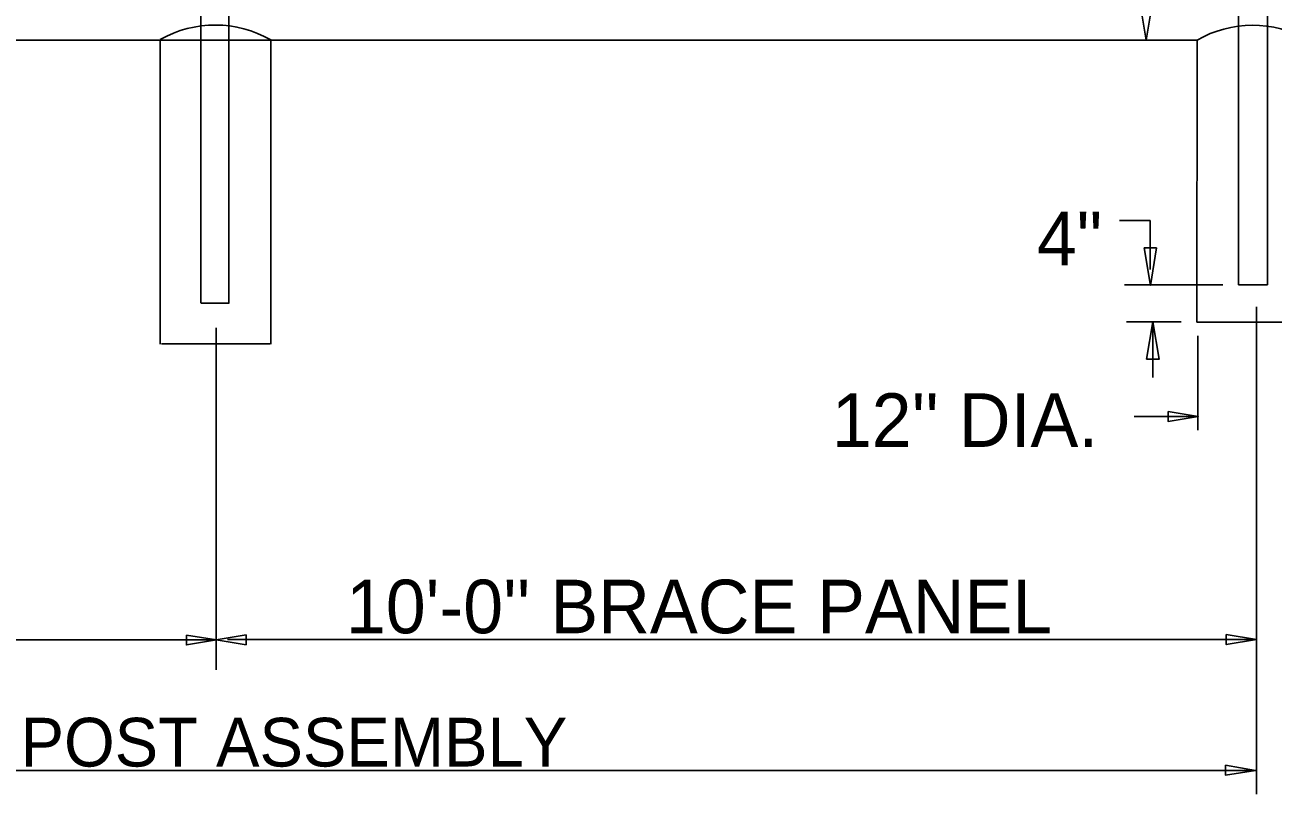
# Model space of a CAD drawing. Extents: x 0 to 1270, y 0 to 830.
# Drawn here: x 1008.4 to 1122.5, y 308.8 to 379.2 of the extents above; entities that cross this region are included whole.
import ezdxf

# ---------------------------------------------------------------- set-up
doc = ezdxf.new("R2010")
doc.units = 0
for name, color, linetype in [('CT_CSHT_GeneralLabel', 7, 'Continuous'), ('CT_Dimensions', 7, 'Continuous'), ('sb_Chainlink Fence', 7, 'Continuous'), ('sb_Existing Concrete', 7, 'Continuous'), ('sb_Existing Structural Steel', 7, 'Continuous')]:
    doc.layers.add(name, color=color, linetype=linetype)

msp = doc.modelspace()

# ---------------------------------------------------------------- linework, layer by layer
at = {"layer": 'CT_Dimensions'}
for p, q in [((1108.44, 361.28), (1111.25, 361.28)), ((1111.25, 356.79), (1111.25, 361.28)), ((1108.91, 355.39), (1117.9, 355.39)), ((1120.99, 339.02), (1120.97, 353.38)), ((1109.09, 352), (1114.08, 352)), ((1111.5, 346.91), (1111.5, 351.99)), ((1025.86, 320.16), (1025.86, 351.44)), ((1115.62, 342.09), (1115.62, 350.72)), ((1109.8, 343.34), (1115.62, 343.34)), ((1120.97, 315.98), (1120.99, 339.02)), ((1120.97, 308.8), (1120.97, 325.43)), ((928.66, 322.9), (1025.84, 322.9)), ((1026.87, 322.93), (1120.97, 322.93)), ((930.83, 310.95), (1120.83, 310.95))]:
    msp.add_line(p, q, dxfattribs=at)
for points in [[(1111.35, 380.5), (1110.89, 377.75), (1110.43, 380.5)], [(1111.85, 358.76), (1111.28, 355.33), (1110.71, 358.76)], [(1110.93, 348.57), (1111.5, 352), (1112.08, 348.57)], [(1112.9, 343.8), (1115.65, 343.34), (1112.9, 342.89)], [(1023.13, 323.35), (1025.87, 322.9), (1023.13, 322.44)], [(1028.59, 322.44), (1025.84, 322.9), (1028.59, 323.36)], [(1118.22, 323.39), (1120.97, 322.93), (1118.22, 322.47)], [(1118.15, 311.43), (1120.9, 310.97), (1118.15, 310.52)]]:
    msp.add_lwpolyline(points, close=True, dxfattribs=at)
at = {"layer": 'sb_Chainlink Fence'}
msp.add_line((832.13, 377.79), (1115.55, 377.76), dxfattribs=at)
at = {"layer": 'sb_Existing Concrete'}
for p, q in [((1020.73, 349.97), (1020.73, 377.81)), ((1030.84, 349.96), (1030.84, 377.78)), ((1115.54, 351.98), (1115.55, 377.76)), ((1125.65, 351.98), (1115.54, 351.98)), ((1020.84, 349.99), (1030.79, 349.99))]:
    msp.add_line(p, q, dxfattribs=at)
for centre, start, end in [((1025.76, 369), 59.953, 119.6876), ((1120.63, 368.98), 60.3124, 120.0471)]:
    msp.add_arc(centre, 10.15, start, end, dxfattribs=at)
at = {"layer": 'sb_Existing Structural Steel'}
for p, q in [((1119.33, 379.04), (1119.33, 442.99)), ((1122, 379.03), (1122, 442.99)), ((1024.45, 378.77), (1024.54, 433.94)), ((1027.02, 378.82), (1027.11, 433.8)), ((1119.33, 355.38), (1119.33, 379.04)), ((1122, 355.38), (1122, 379.04)), ((1024.45, 353.73), (1024.45, 378.77)), ((1027.02, 353.69), (1027.02, 378.82)), ((1122, 355.38), (1119.33, 355.38)), ((1024.45, 353.71), (1027, 353.71)), ((1120.97, 321.45), (1120.97, 325.53))]:
    msp.add_line(p, q, dxfattribs=at)

# ---------------------------------------------------------------- texts
at = {"layer": 'CT_CSHT_GeneralLabel'}
msp.add_text('CORNER POST ASSEMBLY', height=4.455, dxfattribs=at).set_placement((980.49, 311.32))
at = {"layer": 'CT_Dimensions'}
msp.add_text('4"', height=4.901, rotation=360, dxfattribs=at).set_placement((1100.9, 357.16))
for s, height, p in [("12'' DIA. ", 4.901, (1082.15, 340.56)), ("10'-0'' BRACE PANEL", 4.9005, (1037.72, 323.51))]:
    msp.add_text(s, height=height, dxfattribs=at).set_placement(p)

doc.saveas('drawing.dxf')
